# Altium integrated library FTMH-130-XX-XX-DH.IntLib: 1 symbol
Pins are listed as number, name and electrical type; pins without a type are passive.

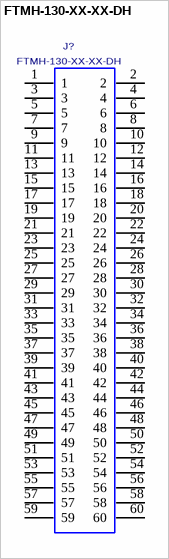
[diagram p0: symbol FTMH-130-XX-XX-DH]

## FTMH-130-XX-XX-DH
designator J?
1MM PITCH, 60PINS, HORIZONTAL SMT TERMINAL STRIP.; MANUFACTURER: SAMTEC
footprint FTMH-130-XX-XX-DH
pins: 1, 2, 3, 4, 5, 6, 7, 8, 9, 10, 11, 12, 13, 14, 15, 16, 17, 18, 19, 20, 21, 22, 23, 24, 25, 26, 27, 28, 29, 30, 31, 32, 33, 34, 35, 36, 37, 38, 39, 40, 41, 42, 43, 44, 45, 46, 47, 48, 49, 50, 51, 52, 53, 54, 55, 56, 57, 58, 59, 60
